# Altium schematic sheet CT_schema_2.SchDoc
size 240 x 321 mm
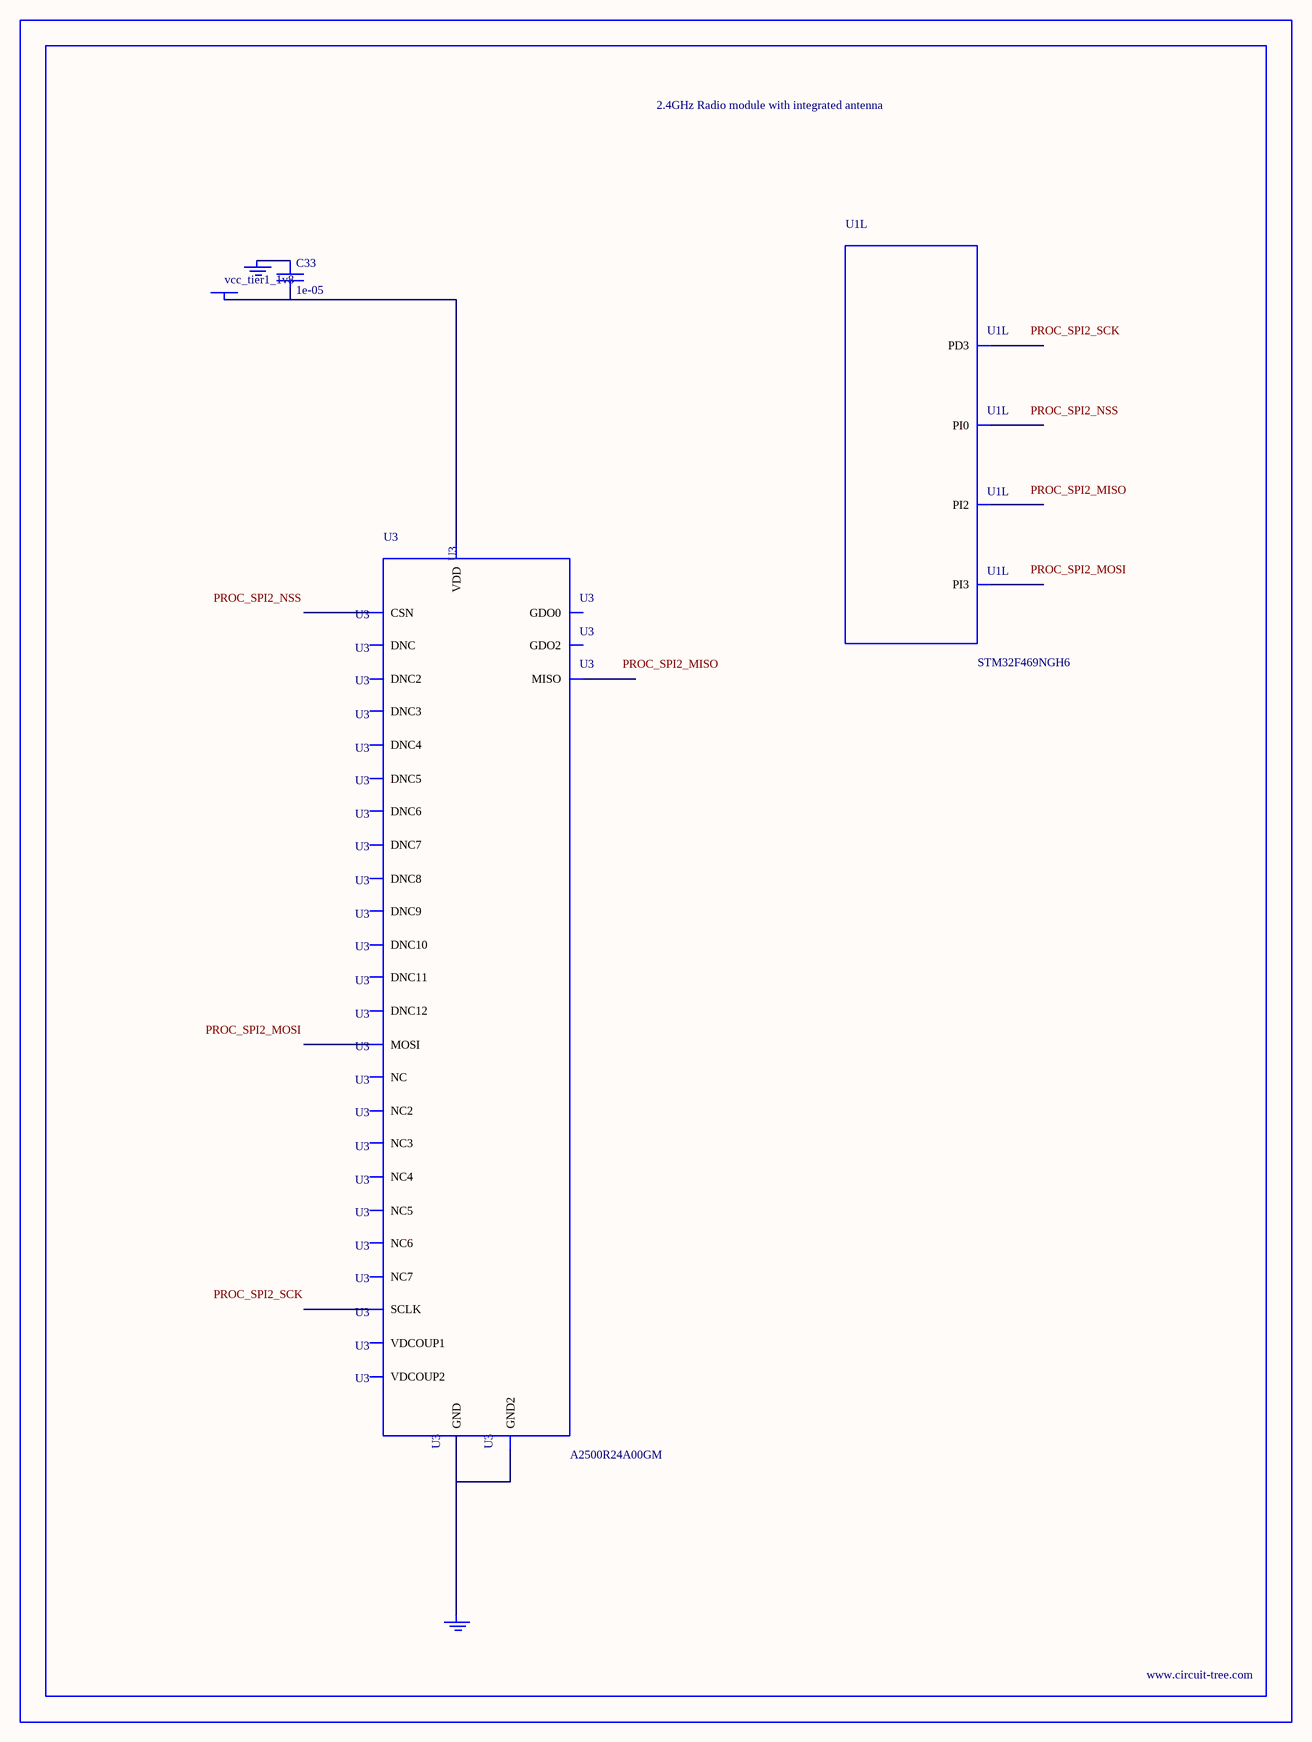
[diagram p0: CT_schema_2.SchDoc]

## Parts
BORDER1  (no value)
C33  1e-05  [C0805]
GND_INSTANCE_1_0  (no value)
GND_INSTANCE_1_1  (no value)
POWER_INSTANCE_1_0  vcc_tier1_1v8
U1  STM32F469NGH6  [TFBGA216]  (part L of 16)
U3  A2500R24A00GM  [A2500R24A00GM]

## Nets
NetC33_1: C33.1 GND_INSTANCE_1_0.0(GND)
NetC33_2: C33.2 POWER_INSTANCE_1_0.0(PWR) U3.18(VDD)
NetGND_INSTANCE_1_1_0: GND_INSTANCE_1_1.0(GND) U3.8(GND) U3.17(GND2)

Not connected (* = marked no-connect by the designer): U1 C11(PD3) C13(PI3) C14(PI2) E14(PI0); U3 1(DNC) 2(DNC2) 3(DNC3) 4(NC) 5(NC2) 6(NC3) 7(VDCOUP1) 9(SCLK) 10(MISO) 11(MOSI) 12(CSN) 13(GDO0) 14(GDO2) 15(VDCOUP2) 16(NC4) 19(NC5) 20(NC6) 21(NC7) 22(DNC4) 23(DNC5) 24(DNC6) 25(DNC7) 26(DNC8) 27(DNC9) 28(DNC10) 29(DNC11) 30(DNC12)

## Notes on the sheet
- Labels drawn without touching a wire or pin: PROC_SPI2_MISO, PROC_SPI2_MOSI, PROC_SPI2_NSS, PROC_SPI2_SCK

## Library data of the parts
BORDER1 = BORDER_PAGE1
C33 = C0805C106K8RACTU
GND_INSTANCE_1_0 GND_INSTANCE_1_1 = GND
POWER_INSTANCE_1_0 = PWR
